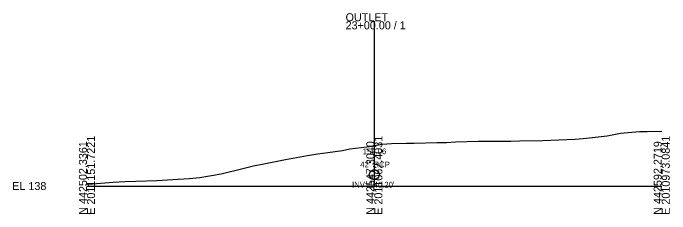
# Model space of a CAD drawing. Extents: x -26 to 1203, y -15 to 9526.
# Drawn here: x 974.3 to 1202.8, y 2990.3 to 3060.2 of the extents above; entities that cross this region are included whole.
import ezdxf

# ---------------------------------------------------------------- set-up
doc = ezdxf.new("R2010")
doc.units = 0
for name, color, linetype in [('Exist Cross Section Cell', 7, 'Continuous'), ('Exist XS Center Line Elevation Label', 7, 'Continuous'), ('Exist XS Ground Line', 7, 'Continuous'), ('Prop XSC Text', 7, 'Continuous')]:
    doc.layers.add(name, color=color, linetype=linetype)

msp = doc.modelspace()

# ---------------------------------------------------------------- linework, layer by layer
at = {"layer": 'Exist Cross Section Cell'}
for p, q in [((1100, 3000), (1100, 3057.34)), ((1000, 3000), (1100, 3000)), ((1100, 3000), (1200, 3000))]:
    msp.add_line(p, q, dxfattribs=at)
at = {"layer": 'Exist XS Ground Line'}
msp.add_lwpolyline([(1000, 3000.74), (1001.93, 3000.81), (1009.15, 3001.33), (1013.12, 3001.56), (1017.04, 3001.67), (1024.32, 3001.98), (1031.7, 3002.38), (1035.52, 3002.66), (1039.28, 3003), (1046.71, 3004.3), (1054.24, 3006.12), (1057.91, 3006.98), (1061.52, 3007.7), (1069.1, 3009.22), (1076.79, 3010.57), (1080.3, 3011.24), (1083.76, 3011.7), (1088.9, 3012.34), (1091.49, 3012.94), (1099.34, 3013.93), (1100, 3014.06), (1102.69, 3014.55), (1106, 3014.78), (1111.24, 3014.95), (1113.89, 3014.94), (1121.89, 3015.14), (1125.08, 3015.2), (1128.23, 3015.34), (1136.28, 3015.59), (1144.43, 3015.65), (1147.47, 3015.67), (1150.47, 3015.71), (1158.67, 3015.83), (1166.98, 3016.19), (1169.87, 3016.32), (1172.71, 3016.56), (1181.06, 3017.5), (1185.71, 3018.35), (1192.26, 3018.96), (1193.16, 3018.99), (1194.95, 3019.02), (1200, 3019.11)], dxfattribs=at)
at = {"layer": 'Prop XSC Text'}
msp.add_circle((1100, 3003.95), 1.75, dxfattribs=at)

# ---------------------------------------------------------------- texts
at = {"layer": 'Exist Cross Section Cell'}
for s, p in [('OUTLET', (1090, 3057.34)), ('23+00.00 / 1', (1090, 3054.54)), ('EL 138', (974, 2998.6))]:
    msp.add_text(s, height=2.8, dxfattribs=at).set_placement(p)
for s, p in [('E 2011151.7221', (1002.8, 2990)), ('E 2011062.4031', (1102.8, 2990)), ('E 2010973.0841', (1202.8, 2990)), ('N 442502.3361', (1000, 2990)), ('N 442547.3040', (1100, 2990)), ('N 442592.2719', (1200, 2990))]:
    msp.add_text(s, height=2.8, rotation=90, dxfattribs=at).set_placement(p)
at = {"layer": 'Exist XS Center Line Elevation Label'}
msp.add_text('152.06', height=2, dxfattribs=at).set_placement((1095.97, 3011.06))
at = {"layer": 'Prop XSC Text'}
for s, p in [('42" RCP', (1095.09, 3006.47)), ("INV=140.20'", (1092.26, 2999.46))]:
    msp.add_text(s, height=2, dxfattribs=at).set_placement(p)

doc.saveas('drawing.dxf')
